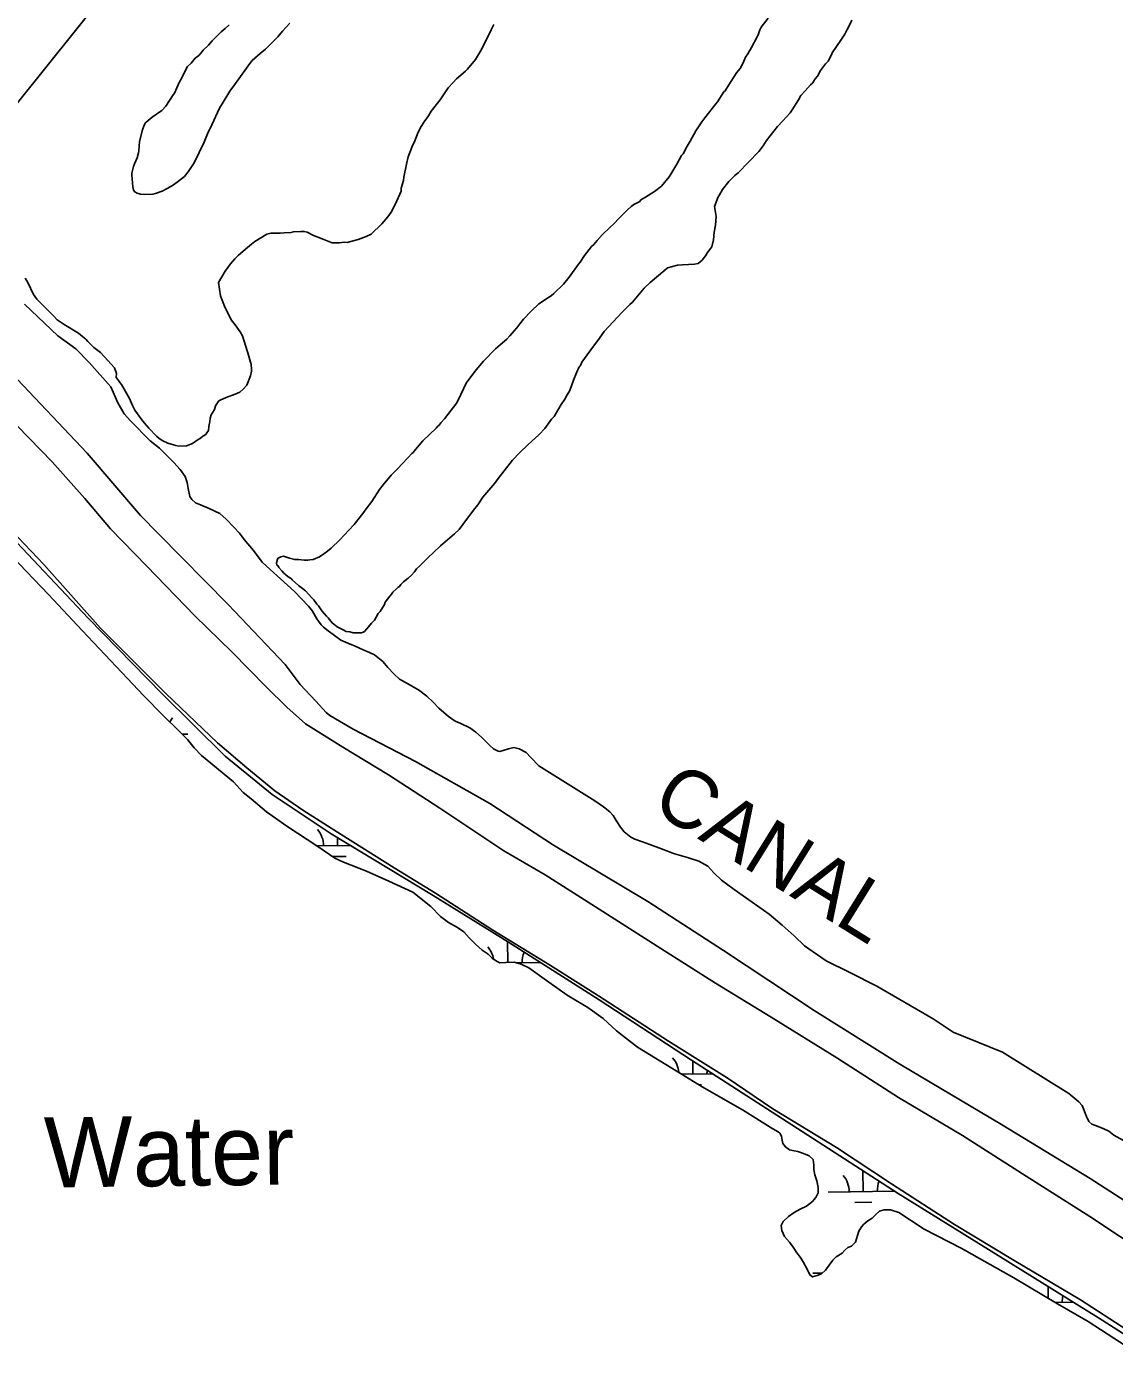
# Model space of a CAD drawing. Extents: x 3775218 to 3813389, y 343470 to 369318.
# Drawn here: x 3806614 to 3808165, y 350782 to 352694 of the extents above; entities that cross this region are included whole.
import ezdxf

# ---------------------------------------------------------------- set-up
doc = ezdxf.new("R2010")
doc.units = 0
for name, color, linetype in [('V-LEVE-TOET', 7, 'Continuous'), ('V-RIVR-IDEN', 7, 'Continuous'), ('V-SITE-VEGE', 7, 'Continuous'), ('V-TOPO-SHOR', 7, 'Continuous'), ('V-WETL-SWMP', 7, 'Continuous')]:
    doc.layers.add(name, color=color, linetype=linetype)

msp = doc.modelspace()

# ---------------------------------------------------------------- linework, layer by layer
at = {"layer": 'V-LEVE-TOET'}
for points in [[(3808216.1, 350941.7), (3808130.1, 350998.3), (3808039.3, 351055.9), (3807948.4, 351113.8), (3807857.1, 351168.2), (3807769.5, 351224.4), (3807675.8, 351282.5), (3807596.3, 351330.9), (3807523.6, 351377), (3807425.3, 351439.6), (3807353.4, 351485.3), (3807294.7, 351519.7), (3807203.2, 351580.5), (3807130.1, 351627.9), (3807065.1, 351667.3), (3807012, 351700.4), (3806985.1, 351724.5), (3806956, 351752.8), (3806906.6, 351803.4), (3806854.1, 351854.4), (3806785.8, 351925.3), (3806733.8, 351978.4), (3806697.1, 352021.7), (3806650.6, 352073.8), (3806584.6, 352141.8)], [(3806547.9, 352022.7), (3806638.9, 351927.6), (3806719.7, 351836.8), (3806812.8, 351744), (3806886.2, 351673.6), (3806928.4, 351638), (3806968, 351605.3), (3807008.2, 351577.5), (3807062.6, 351543.1), (3807138.3, 351495.5), (3807197, 351459.4), (3807279, 351406.8), (3807359.5, 351357.1), (3807429.3, 351313), (3807529.4, 351248.5), (3807613, 351196.3), (3807678.3, 351151.9), (3807768.7, 351097), (3807847.4, 351045), (3807937.3, 350987.3), (3808022.1, 350935.8), (3808116.5, 350879.6), (3808182.7, 350837.2)]]:
    msp.add_lwpolyline(points, dxfattribs=at)
at = {"layer": 'V-SITE-VEGE'}
for points in [[(3806902.8, 352696.8), (3806897.4, 352691.6), (3806891.4, 352686.9), (3806886.6, 352682.3), (3806878.8, 352674.2), (3806873.3, 352667.8), (3806866.1, 352660.8), (3806863.1, 352656.7), (3806859.5, 352653.3), (3806854.7, 352649.2), (3806848.6, 352642.2), (3806843.8, 352637.6), (3806837.7, 352626.5), (3806834.6, 352619.4), (3806832.2, 352615.4), (3806828.5, 352607.2), (3806824.8, 352599.5), (3806823, 352597.2), (3806812.6, 352580.9), (3806807.2, 352574.5), (3806793.4, 352565.3), (3806787.4, 352560.6), (3806783.8, 352557.2), (3806782, 352553.6), (3806779.5, 352547.2), (3806775, 352530.7), (3806774.2, 352517.1), (3806773.5, 352514.2), (3806771.6, 352507.1), (3806767.9, 352498.9), (3806766.7, 352494.8), (3806764.1, 352485.4), (3806764.1, 352483.1), (3806765.5, 352465.9), (3806766.6, 352461.1), (3806768.4, 352458.7), (3806771.9, 352456.9), (3806776.6, 352455.6), (3806781.9, 352454.9), (3806794.3, 352455.3), (3806797.9, 352456.4), (3806807.4, 352459.8), (3806814.6, 352463.8), (3806822.3, 352467.8), (3806828.9, 352472.4), (3806839.1, 352480.5), (3806844.6, 352487.5), (3806853.1, 352500.3), (3806867.2, 352529.6), (3806872.1, 352541.3), (3806878.3, 352554.2), (3806889.4, 352578.2), (3806893, 352584.1), (3806904, 352602.2), (3806911.9, 352613.3), (3806932.5, 352641.9), (3806935.6, 352645.9), (3806947, 352655.8), (3806954.8, 352662.1), (3806965, 352672.6), (3806972.2, 352679.5), (3806978.9, 352687.7), (3806989.7, 352699.3)], [(3807280.1, 352697.4), (3807276.4, 352689.8), (3807272.7, 352681.5), (3807261.1, 352659.3), (3807254.4, 352647.6), (3807242.9, 352633.6), (3807239.9, 352630.7), (3807227.2, 352619.7), (3807222.4, 352614.5), (3807215.2, 352607), (3807205.5, 352593), (3807203.6, 352590), (3807190.9, 352573.7), (3807187.3, 352567.3), (3807181.2, 352558.5), (3807176.9, 352552.1), (3807172.6, 352543.9), (3807167.7, 352531.6), (3807164, 352523.4), (3807158.4, 352508.7), (3807155.8, 352498.1), (3807151.9, 352479.9), (3807151.3, 352475.2), (3807148.1, 352464), (3807148, 352459.9), (3807140, 352441.7), (3807133.9, 352430), (3807129, 352423), (3807120.6, 352413.1), (3807105.5, 352398.6), (3807098.4, 352395.2), (3807087.1, 352390.7), (3807071, 352386.8), (3807067.5, 352386.9), (3807059.8, 352385.9)], [(3807068.1, 351970.6), (3807072.9, 351976.4), (3807081.4, 351984.5), (3807093.5, 352000.2), (3807098.3, 352007.2), (3807106.2, 352017.7), (3807117.2, 352034.7), (3807122.6, 352041.1), (3807134.1, 352055), (3807136.5, 352057.4), (3807144.3, 352065.5), (3807149.2, 352070.7), (3807158.2, 352080), (3807163.6, 352085.8), (3807165.4, 352087.5), (3807168.5, 352091.6), (3807179.3, 352103.8), (3807198, 352121.8), (3807200.4, 352124.7), (3807202.2, 352126.5), (3807204.6, 352129.4), (3807210, 352135.2), (3807227.6, 352157.9), (3807233.2, 352170.2), (3807241.1, 352186), (3807253.3, 352202.9), (3807257.5, 352208.2), (3807265.4, 352217.5), (3807282.8, 352234.9), (3807289.4, 352240.7), (3807299, 352248.8), (3807303.3, 352253.4), (3807312.9, 352265.1), (3807317.2, 352270.9), (3807322.6, 352277.3), (3807332.9, 352288.3), (3807344.3, 352299.3), (3807359.9, 352309.1), (3807362.2, 352310.8), (3807365.8, 352313.7), (3807379.7, 352327.1), (3807387.6, 352337), (3807400.9, 352355.6), (3807403.3, 352358.5), (3807409.4, 352367.9), (3807419.7, 352380.7), (3807422.7, 352383.6), (3807427.5, 352389.4), (3807434.8, 352397.5), (3807446.2, 352408.6), (3807451.6, 352413.2), (3807458.9, 352421.3), (3807470.3, 352432.9), (3807476.3, 352438.1), (3807479.9, 352441), (3807488.3, 352445), (3807490.1, 352447.3), (3807496.7, 352451.4), (3807509.2, 352459.4), (3807519.4, 352466.9), (3807530.3, 352480.3), (3807532.7, 352483.8), (3807538.2, 352493.7), (3807541.3, 352498.4), (3807548, 352510.7), (3807550.4, 352513), (3807555.9, 352524.1), (3807560.2, 352531.1), (3807568.1, 352545.8), (3807570, 352548.7), (3807576.7, 352558.6), (3807580.9, 352564.4), (3807596.6, 352584.2), (3807599.1, 352587.2), (3807608.2, 352601.2), (3807610, 352602.9), (3807615.5, 352611.1), (3807626.4, 352628.6), (3807631.3, 352634.4), (3807635.6, 352642.6), (3807639.3, 352650.8), (3807642.3, 352655.5), (3807647.8, 352664.3), (3807655.7, 352679.5), (3807657, 352682.4), (3807659.5, 352689.5), (3807661.3, 352693.6), (3807671.6, 352706.4)], [(3807790.9, 352703.6), (3807786, 352693.6), (3807784.2, 352690.1), (3807780.5, 352683.7), (3807775, 352674.9), (3807762.9, 352656.8), (3807761.6, 352653.9), (3807756.8, 352645.1), (3807753.1, 352641), (3807745.9, 352631.7), (3807741.6, 352623.5), (3807738.6, 352620), (3807737.3, 352618.3), (3807734.9, 352614.2), (3807731.9, 352611.3), (3807724.1, 352602.6), (3807718, 352596.2), (3807714.9, 352589.7), (3807705.8, 352575.7), (3807702.8, 352571.6), (3807692.5, 352560), (3807684.7, 352551.9), (3807669, 352532.1), (3807664.1, 352524.5), (3807658, 352516.3), (3807628.5, 352486.1), (3807623.7, 352482.1), (3807615.3, 352473.4), (3807606.2, 352462.3), (3807601.9, 352454.7), (3807600.1, 352451.8), (3807595.1, 352437.7), (3807597.2, 352423.5), (3807596.4, 352411.1), (3807594.4, 352401.1), (3807593.6, 352390.5), (3807591.1, 352380.5), (3807589.9, 352378.7), (3807585, 352372.3), (3807582, 352367.6), (3807577.1, 352361.2), (3807574.7, 352358.9), (3807571.7, 352356.6), (3807566.4, 352355.5), (3807549.2, 352354.6), (3807542.1, 352354.2), (3807527.9, 352350.3), (3807524.3, 352347.4), (3807503.3, 352329.5), (3807494.8, 352321.4), (3807477.9, 352301.6), (3807474.3, 352298.1), (3807463.5, 352287.1), (3807437.5, 352259.8)], [(3807059.8, 352385.9), (3807049.7, 352386.1), (3807038, 352391), (3807029.2, 352394.1), (3807023.3, 352396.6), (3807014, 352401.5), (3807009.8, 352402.2), (3807005.1, 352402.3), (3806994.5, 352401.9), (3806990.9, 352400.7), (3806981.4, 352400.3), (3806976.1, 352399.8), (3806962.5, 352400.1), (3806956.6, 352398.4), (3806939.8, 352388.1), (3806935, 352384.1), (3806929, 352379.4), (3806916.4, 352368.4), (3806911, 352363.2), (3806905, 352356.2), (3806897.1, 352345.8), (3806887.9, 352329.4), (3806890.5, 352310.4), (3806892.2, 352306.8), (3806896.2, 352296.1), (3806905.9, 352276.4), (3806911.6, 352269.2), (3806918.5, 352259.1), (3806922, 352253.7), (3806928.7, 352232.3), (3806929.8, 352229.3), (3806934.2, 352212.7), (3806934.7, 352206.2), (3806934.6, 352203.2), (3806933.3, 352196.7), (3806928.3, 352183.2), (3806922.9, 352177.4), (3806918.1, 352173.4), (3806909.2, 352169.4), (3806900.9, 352166.6), (3806891.3, 352162.6), (3806888.3, 352160.9), (3806885.3, 352156.8), (3806883.5, 352153.9), (3806882.2, 352148.6), (3806877.3, 352141), (3806876.1, 352136.3), (3806875.4, 352131.6), (3806874.1, 352124.6), (3806873.4, 352118.7), (3806870.9, 352115.2), (3806869.7, 352112.8), (3806865.5, 352110.5), (3806861.9, 352107.6), (3806858.9, 352105.9), (3806850.6, 352100.2), (3806842.2, 352096.8), (3806831, 352096.4), (3806826.9, 352097.1), (3806820.4, 352099), (3806815.7, 352100.8), (3806807.5, 352104.5), (3806802.8, 352107.6), (3806799.3, 352110.6), (3806788.3, 352122), (3806782.5, 352129.2), (3806778.5, 352134), (3806768.7, 352147.8), (3806765.3, 352154.4), (3806760.7, 352164.5), (3806749.3, 352184.2), (3806747, 352187.2), (3806744.1, 352191.4), (3806741.8, 352194.4), (3806742.5, 352199.7), (3806739.7, 352208), (3806725.2, 352223.7), (3806719.4, 352229.7), (3806710.1, 352236.9), (3806701.4, 352245.4), (3806698.5, 352249), (3806693.8, 352252.6), (3806688, 352257.4), (3806667.6, 352269.6), (3806657.6, 352276.3), (3806652.4, 352282.3), (3806638.5, 352296.2), (3806628.6, 352305.8), (3806624, 352312.4), (3806616.1, 352329.7), (3806612, 352335.7)], [(3807437.5, 352259.8), (3807428.4, 352247), (3807422.4, 352238.8), (3807409.6, 352221.3), (3807406, 352216), (3807404.2, 352212.5), (3807401.7, 352208.4), (3807398, 352200.8), (3807393.7, 352190.3), (3807388.7, 352175.6), (3807385, 352169.7), (3807381.4, 352163.3), (3807376.5, 352155.7), (3807366.1, 352138.8), (3807362.5, 352134.7), (3807352.8, 352121.3), (3807345, 352113.2), (3807328.7, 352098.1), (3807317.3, 352087.1), (3807307.1, 352076.6), (3807291.9, 352056.8), (3807286.5, 352050.4), (3807281.6, 352043.4), (3807264.7, 352023.6), (3807257.4, 352012.6), (3807251.4, 352005), (3807236.2, 351984.6), (3807230.8, 351977.6), (3807224.1, 351971.2), (3807204.3, 351954.4), (3807193.5, 351944), (3807187.5, 351938.8), (3807174.2, 351925.5), (3807170, 351921.4), (3807167, 351917.3), (3807162.8, 351912.7), (3807158, 351908), (3807151.4, 351902.8), (3807147.7, 351899.3), (3807145.9, 351896.4), (3807144.1, 351895.3), (3807141.7, 351893), (3807136.3, 351888.3), (3807134.5, 351885.4), (3807132.1, 351882.5), (3807125.4, 351873.8), (3807124.2, 351870.8), (3807118.1, 351860.9), (3807115.6, 351858), (3807110.2, 351848.6), (3807105.9, 351844), (3807099.3, 351835.8), (3807095.7, 351832.4), (3807093.9, 351831.2), (3807091.5, 351830.1), (3807079.7, 351830.3), (3807075, 351831.6), (3807069.7, 351832.2), (3807065.6, 351834.7), (3807061.5, 351836.5), (3807056.8, 351839), (3807049.8, 351844.4), (3807044, 351851.6), (3807041.7, 351854), (3807035.3, 351861.8), (3807031.3, 351867.2), (3807030.2, 351869), (3807027.8, 351871.4), (3807023.8, 351877.4), (3807020.9, 351880.4), (3807011.6, 351890.1), (3807007.6, 351893.7), (3807001.7, 351897.9), (3806993, 351905.8), (3806991.3, 351907.6), (3806987.2, 351910), (3806983.1, 351913.6), (3806980.8, 351915.5), (3806977.9, 351918.5), (3806973.8, 351923.3), (3806972.7, 351925.7), (3806970.9, 351926.9), (3806970.4, 351929.8), (3806971, 351932.2), (3806971.7, 351935.1), (3806972.9, 351936.9), (3806976.5, 351938.6), (3806980.6, 351939.7), (3806988.9, 351936.6), (3806996.5, 351934.7), (3807001.8, 351934.6), (3807010.1, 351933.8), (3807014.8, 351933.7), (3807017.8, 351934.3), (3807022.5, 351934.8), (3807032, 351938.7), (3807038, 351942.8), (3807043.4, 351946.8), (3807048.2, 351950.8), (3807060.9, 351963), (3807068.1, 351970.6)]]:
    msp.add_lwpolyline(points, dxfattribs=at)
at = {"layer": 'V-TOPO-SHOR'}
for points in [[(3807368, 353557.4), (3807303.8, 353474.1), (3807199.1, 353339.5), (3807081.5, 353191), (3806942.6, 353009.7), (3806826.1, 352868.3), (3806722.3, 352737.2), (3806603, 352587.8), (3806488.1, 352442)], [(3806611.1, 352298.9), (3806658.8, 352253.6), (3806684.2, 352235.2), (3806703.6, 352215.7), (3806734.5, 352181), (3806744.2, 352158.2), (3806753.4, 352142.3), (3806762.2, 352132.3), (3806790.5, 352104), (3806803.6, 352093.3), (3806815.5, 352081.8), (3806824.1, 352072.9), (3806833, 352062.9), (3806840.1, 352053.3), (3806843.3, 352044.7), (3806844.7, 352035.8), (3806846.9, 352024.8), (3806849.7, 352020.3), (3806854.9, 352015.7), (3806862, 352012.7), (3806874.6, 352007.6), (3806889.5, 352000.2), (3806898.8, 351992.4), (3806909.8, 351980.9), (3806917.6, 351972.3), (3806924.3, 351963.5), (3806937.5, 351947.5), (3806949.9, 351931.1), (3806961.4, 351920.5), (3806976.1, 351907.2), (3806995.9, 351889), (3807005.6, 351879.3), (3807015.9, 351868.1)], [(3806592.6, 352200.6), (3806700.3, 352086.3), (3806776.8, 351997.4), (3806802.4, 351971.5), (3806901.5, 351870.7), (3806983, 351785.1), (3807004.4, 351756.5), (3807026.6, 351732.8), (3807041.4, 351717), (3807046.6, 351712.7), (3807079.6, 351692.8), (3807168.7, 351647.1), (3807274.4, 351587), (3807365.6, 351527.6), (3807499.7, 351447.3), (3807607.8, 351377.8), (3807736.9, 351292.1), (3807859.3, 351215.6), (3808003.9, 351129.4), (3808130.3, 351052.8), (3808252.4, 350974.2)], [(3806583.1, 351950.2), (3806645.5, 351885), (3806693.3, 351833.7), (3806758.1, 351765.3), (3806780.8, 351740.9), (3806808.6, 351713.1), (3806832.3, 351689.8), (3806843.6, 351678.4), (3806853.1, 351666.5), (3806863.7, 351655.6), (3806909.3, 351618.2), (3806922.8, 351603), (3806934.2, 351593.8), (3806956.4, 351575.1), (3806985.2, 351555), (3807029.3, 351525.9), (3807053.7, 351509.2), (3807066.2, 351503.6), (3807099, 351490.6), (3807130.6, 351476.2), (3807164.8, 351460.8), (3807190.7, 351440.3), (3807204.1, 351426.1), (3807215.8, 351417.3), (3807228.4, 351410.5), (3807237.4, 351404), (3807245.2, 351395.8), (3807254, 351386.4), (3807263.8, 351378.1), (3807272.2, 351372.4), (3807278.1, 351366.5), (3807283.9, 351362.4), (3807289.1, 351359.9), (3807297.3, 351360.4), (3807309.4, 351361.1), (3807319.4, 351358.1), (3807330.1, 351352.9), (3807355.2, 351334.7), (3807384.7, 351314.1), (3807414.3, 351296.6), (3807436.1, 351280.5), (3807455.1, 351262.9), (3807485.3, 351239.8), (3807534.2, 351210.1), (3807577.5, 351183.2), (3807634.8, 351150.7), (3807677.9, 351123.5), (3807685.8, 351119.2), (3807687.9, 351117.5), (3807690.4, 351113.1), (3807691.2, 351107.5), (3807692.5, 351102.7), (3807696.1, 351097.7), (3807702, 351093.5), (3807708.6, 351091.9), (3807713.8, 351091), (3807721.8, 351088.5), (3807729.8, 351085.2), (3807735.5, 351079.6), (3807736.6, 351072.2), (3807736.5, 351065.3), (3807738, 351057.9), (3807740.6, 351049.2), (3807742.7, 351039.7), (3807742.5, 351032.1), (3807739.3, 351025.6), (3807734.8, 351020), (3807726.2, 351013.3), (3807716.9, 351009.1), (3807708.7, 351004.2), (3807700.2, 350998.7), (3807692.8, 350991.5), (3807690.1, 350985.5), (3807690.9, 350978.7), (3807694.5, 350969.9), (3807701.7, 350961.7), (3807707.1, 350954.8), (3807712.5, 350946.5), (3807717.4, 350939.9), (3807721.9, 350932.9), (3807727.2, 350923.5), (3807730.9, 350915.6), (3807734.8, 350912.4), (3807741.1, 350914.2), (3807747.5, 350917), (3807753.2, 350922), (3807758.6, 350929.2), (3807763.5, 350936.2), (3807768.6, 350941.1), (3807776.8, 350946.2), (3807780.6, 350950.3), (3807785, 350954.3), (3807790.1, 350956.4), (3807795.8, 350962), (3807798.6, 350971.4), (3807800.9, 350977.8), (3807804.5, 350983.7), (3807808, 350987.6)], [(3807015.9, 351868.1), (3807021.7, 351861.2), (3807028.1, 351850.3), (3807034.1, 351841.7), (3807037.7, 351838.4), (3807044.2, 351833), (3807062.1, 351819.7), (3807072.2, 351815.4), (3807082.5, 351811.1), (3807094, 351806.3), (3807103.2, 351802.5), (3807110.2, 351799.1), (3807122, 351789.6), (3807129.2, 351781), (3807137.7, 351771.7), (3807146, 351764.4), (3807158.8, 351757.1), (3807172.7, 351749.2), (3807184.7, 351740.2), (3807193.9, 351731.3), (3807202, 351722.9), (3807215.6, 351711.3), (3807225.3, 351704.5), (3807233.3, 351701), (3807245.9, 351695), (3807254.8, 351688.7), (3807262.9, 351681.7), (3807269, 351675.4), (3807274.6, 351669.9), (3807280, 351664.9), (3807284.8, 351662.6), (3807286.6, 351661.8), (3807288.9, 351661.1), (3807301.1, 351665.1), (3807308.9, 351666.9), (3807316.5, 351665), (3807326.5, 351659.6), (3807333, 351652.7), (3807344.5, 351640.7), (3807386.3, 351614.7), (3807424.1, 351590.9), (3807436.6, 351582.2), (3807445.6, 351575.1), (3807450.4, 351569.9), (3807454.8, 351562.8), (3807460.7, 351553.3), (3807466.3, 351546.8), (3807475.8, 351538.9), (3807481.3, 351536.1), (3807492.3, 351532.3), (3807502.6, 351528.7), (3807519.4, 351522.6), (3807529.5, 351518.5), (3807536.4, 351516), (3807556.6, 351510.2), (3807572.7, 351504.8), (3807585.2, 351497.6), (3807594, 351488.3), (3807605, 351477.7), (3807622.9, 351464.4), (3807648.6, 351446.6), (3807672.9, 351429.5), (3807691.6, 351413.8), (3807708.3, 351398.6), (3807723.4, 351384.2), (3807754, 351362.8), (3807787.9, 351346.3), (3807826.5, 351327), (3807906.7, 351280), (3807935.1, 351261.4), (3808005.7, 351232.9), (3808100.3, 351174), (3808114.4, 351162), (3808119.1, 351156.7), (3808125.3, 351140.9), (3808128.5, 351134.1), (3808132.8, 351130.2), (3808141.8, 351126.7), (3808150.2, 351123.4), (3808156.9, 351120.2), (3808164.1, 351114.6), (3808196.1, 351097)], [(3807808, 350987.6), (3807813.5, 350992.4), (3807819.6, 350996.3), (3807825.4, 351002), (3807830.3, 351005.9), (3807836.8, 351007.9), (3807845.8, 351007.8), (3807857.6, 351004), (3807893.9, 350980.5), (3807946.6, 350953.2), (3808021.8, 350911.3), (3808084, 350874), (3808127.5, 350848.9), (3808182, 350813.8)]]:
    msp.add_lwpolyline(points, dxfattribs=at)
at = {"layer": 'V-WETL-SWMP'}
for p, q in [((3806836.3, 351685.8), (3806843.9, 351685.9)), ((3807057.6, 351527), (3807057.4, 351538.5)), ((3807028.2, 351526.6), (3807076.1, 351527.3)), ((3807050.3, 351511.5), (3807069.8, 351511.8)), ((3807300.4, 351360.6), (3807300, 351390.1)), ((3807313.6, 351359.8), (3807346.9, 351360.3)), ((3807564.2, 351201.5), (3807563.9, 351220.3)), ((3807548.4, 351201.2), (3807592.4, 351201.9)), ((3807572.8, 351186.2), (3807576.4, 351186.2)), ((3807807, 351034.1), (3807806.6, 351063.8)), ((3807757, 351033.4), (3807851.8, 351034.7)), ((3807795.2, 351018.5), (3807819.2, 351018.8)), ((3807735.2, 350917.6), (3807748.4, 350917.8)), ((3808070.6, 350882), (3808070.4, 350898.7)), ((3808080.6, 350876), (3808106.4, 350876.4))]:
    msp.add_line(p, q, dxfattribs=at)
for points in [[(3805908.2, 352705), (3806034.2, 352566.8), (3806158.2, 352432.2), (3806276.8, 352305.6), (3806399.6, 352176), (3806496.2, 352072.1), (3806584.5, 351975.5), (3806701.8, 351851.1), (3806807.5, 351743.3), (3806897.5, 351654.5), (3806964.5, 351599.9), (3807048.6, 351543.9), (3807194, 351456.1), (3807301, 351389.5), (3807430.3, 351307.2), (3807562.3, 351221.3), (3807720, 351119.7), (3807856.8, 351031.5), (3807985.5, 350951.3), (3808142.6, 350854), (3808289.9, 350759.8)], [(3807798.6, 350971.4), (3807795.8, 350962), (3807790.1, 350956.4), (3807785, 350954.3), (3807780.6, 350950.3), (3807776.8, 350946.2), (3807768.6, 350941.1), (3807763.5, 350936.2), (3807758.6, 350929.2), (3807753.2, 350922), (3807747.5, 350917), (3807741.1, 350914.2), (3807734.8, 350912.4), (3807730.9, 350915.6), (3807727.2, 350923.5), (3807721.9, 350932.9), (3807717.4, 350939.9), (3807712.5, 350946.5), (3807707.1, 350954.8), (3807701.7, 350961.7), (3807694.5, 350969.9), (3807690.9, 350978.7), (3807690.1, 350985.5), (3807692.8, 350991.5), (3807700.2, 350998.7), (3807708.7, 351004.2), (3807716.9, 351009.1), (3807726.2, 351013.3), (3807734.8, 351020), (3807739.3, 351025.6), (3807742.5, 351032.1), (3807742.7, 351039.7), (3807740.6, 351049.2), (3807738, 351057.9), (3807736.5, 351065.3), (3807736.6, 351072.2), (3807735.5, 351079.6), (3807729.8, 351085.2), (3807721.8, 351088.5), (3807713.8, 351091), (3807708.6, 351091.9), (3807702, 351093.5), (3807696.2, 351097.7), (3807692.5, 351102.7), (3807691.2, 351107.5), (3807690.4, 351113.1), (3807687.9, 351117.5), (3807685.8, 351119.2), (3807677.9, 351123.5), (3807634.8, 351150.7), (3807577.5, 351183.2), (3807534.2, 351210.1), (3807485.3, 351239.8), (3807455.1, 351262.9), (3807436.1, 351280.5), (3807414.3, 351296.6), (3807384.7, 351314.1), (3807355.3, 351334.7), (3807330.1, 351352.9), (3807319.4, 351358.1), (3807309.4, 351361.1), (3807297.2, 351360.4), (3807289.1, 351359.9), (3807283.9, 351362.4), (3807278.1, 351366.5), (3807272.2, 351372.4), (3807263.8, 351378.1), (3807254, 351386.4), (3807245.2, 351395.8), (3807237.4, 351404), (3807228.4, 351410.5), (3807215.8, 351417.3), (3807204.1, 351426.1), (3807190.7, 351440.3), (3807164.8, 351460.8), (3807130.6, 351476.2), (3807099, 351490.6), (3807066.2, 351503.6), (3807053.7, 351509.2), (3807029.3, 351525.9), (3806985.2, 351555), (3806956.4, 351575.1), (3806934.2, 351593.8), (3806922.8, 351603), (3806909.3, 351618.2), (3806863.7, 351655.6), (3806853.1, 351666.5), (3806843.6, 351678.4), (3806832.3, 351689.8), (3806808.6, 351713.1), (3806780.8, 351740.9), (3806758.1, 351765.3), (3806693.3, 351833.7), (3806645.5, 351885), (3806583.1, 351950.2)], [(3808182, 350813.8), (3808127.5, 350848.9), (3808084, 350874), (3808021.8, 350911.3), (3807946.6, 350953.2), (3807893.9, 350980.5), (3807857.6, 351004), (3807845.8, 351007.8), (3807836.8, 351007.9), (3807830.3, 351005.9), (3807825.4, 351002), (3807819.6, 350996.3), (3807813.5, 350992.4), (3807808, 350987.6), (3807804.5, 350983.7), (3807800.9, 350977.8), (3807798.6, 350971.4)]]:
    msp.add_lwpolyline(points, dxfattribs=at)
for centre, start, end in [((3806849.1, 351686.4), 140.0365, 150.997), ((3807002.4, 351526.7), 0.0365, 41.5802), ((3807245.2, 351359.3), 9.5494, 41.5802), ((3807355.7, 351360.9), 156.0478, 181.5802), ((3807508.9, 351201.2), 4.5842, 41.5802), ((3807619.4, 351202.7), 172.974, 181.5802), ((3807751.8, 351033.8), 0.0365, 41.5802), ((3807862.2, 351035.3), 157.2811, 181.5802), ((3808125.9, 350877.2), 166.2901, 181.5802)]:
    msp.add_arc(centre, 35.2, start, end, dxfattribs=at)

# ---------------------------------------------------------------- texts
at = {"layer": 'V-RIVR-IDEN'}
for s, height, rotation, p in [('CANAL', 83, 328.1278, (3807501.7, 351579.9)), ('Water', 100, 0.7588, (3806639.8, 351039.6))]:
    msp.add_text(s, height=height, rotation=rotation, dxfattribs=at).set_placement(p)

doc.saveas('drawing.dxf')
